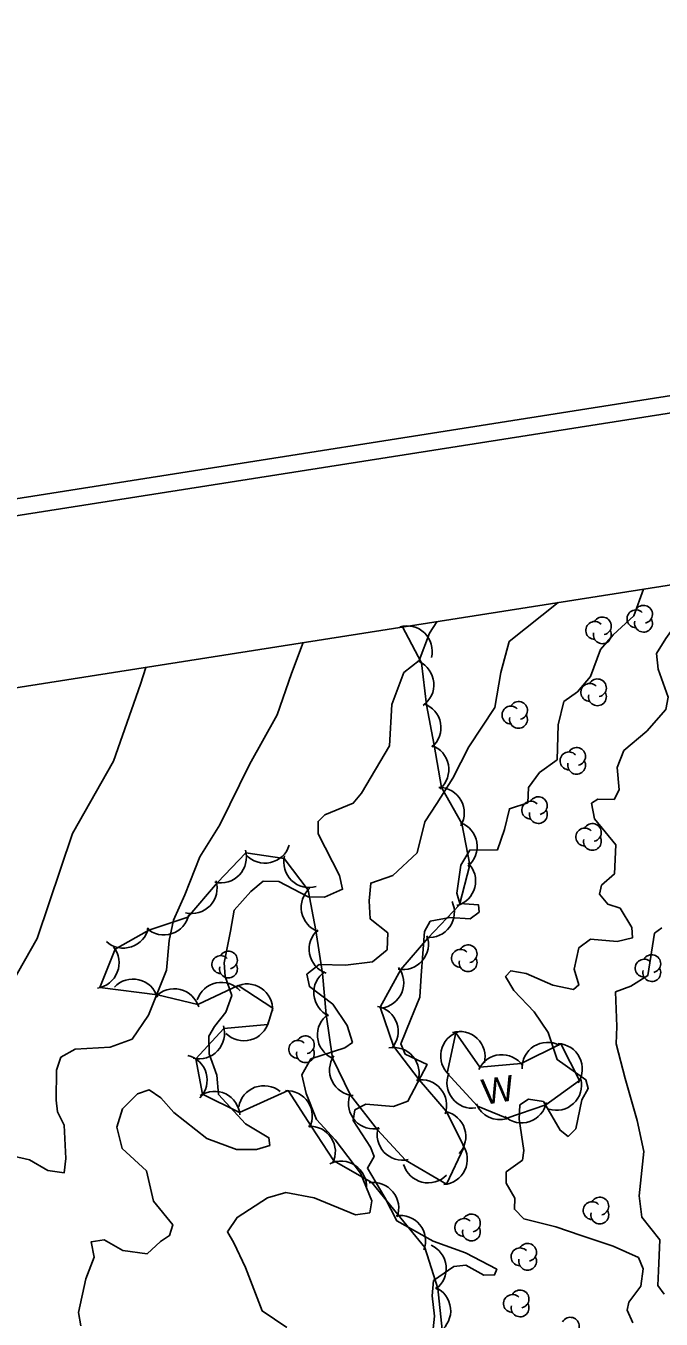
# Model space of a CAD drawing. Extents: x 646142 to 649934, y 5874075 to 5876351.
# Drawn here: x 646903.8 to 646978.6, y 5875820.6 to 5875973 of the extents above; entities that cross this region are included whole.
import ezdxf

# ---------------------------------------------------------------- set-up
doc = ezdxf.new("R2010")
doc.units = 0
for name, color, linetype in [('Niveau 1', 7, 'Continuous'), ('Niveau 2', 7, 'Continuous'), ('Niveau 44', 7, 'Continuous'), ('Niveau 60', 7, 'Continuous')]:
    doc.layers.add(name, color=color, linetype=linetype)

msp = doc.modelspace()

# ---------------------------------------------------------------- linework, layer by layer
at = {"layer": 'Niveau 1'}
for points in [[(646902.34, 5875839.82), (646904.22, 5875839.4), (646906.37, 5875838.15), (646908.3, 5875837.85), (646908.51, 5875839.56), (646908.32, 5875843.47), (646907.52, 5875845.06), (646907.37, 5875846.43), (646907.39, 5875849.96), (646907.92, 5875851.47), (646909.59, 5875852.42), (646913.71, 5875852.66), (646916.31, 5875853.6), (646918.24, 5875856.43), (646920.37, 5875861.72), (646920.68, 5875865.23), (646921.17, 5875867.6), (646922.52, 5875870.6), (646924.28, 5875875.09), (646926.63, 5875878.84), (646930.12, 5875885.96), (646933.4, 5875891.79), (646935.06, 5875896.68), (646936.43, 5875900.31)], [(646978.94, 5875823.57), (646978.2, 5875824.59), (646978.31, 5875826.32), (646978.45, 5875829.97), (646976.33, 5875832.63), (646976.01, 5875835.13), (646976.57, 5875840.37), (646975.79, 5875844.03), (646974.36, 5875848.96), (646973.3, 5875853.05), (646973.38, 5875855.08), (646973.24, 5875859.16), (646975.02, 5875859.85), (646977.02, 5875861.09), (646977.83, 5875866.07), (646977.83, 5875866.07), (646978.69, 5875866.73)]]:
    msp.add_lwpolyline(points, dxfattribs=at)
at = {"layer": 'Niveau 2'}
for points in [[(646971.57, 5875871.75), (646973.11, 5875873.06), (646973.28, 5875876.48), (646970.77, 5875879.57), (646970.41, 5875881.39), (646971.16, 5875881.87), (646973.07, 5875881.83), (646973.65, 5875882.98), (646973.43, 5875885.62), (646974.21, 5875887.6), (646976.92, 5875889.89), (646979.14, 5875892.43), (646979.45, 5875893.9), (646978.24, 5875897.19), (646978.05, 5875899.02), (646979.14, 5875900.8), (646980.66, 5875902.86), (646980.78, 5875905.65), (646982.82, 5875907.12), (646986.02, 5875908.02), (646988.53, 5875908.5)], [(646951.75, 5875829.82), (646947.49, 5875832.2), (646947.49, 5875832.2), (646946.05, 5875834.97), (646944.02, 5875838.42), (646944.79, 5875839.77), (646944.39, 5875840.88), (646942.33, 5875844.03), (646942.54, 5875845.27), (646943.84, 5875845.94), (646947.07, 5875845.68), (646948.78, 5875846.28), (646951.05, 5875850.63), (646948.47, 5875851.83), (646947.94, 5875853.04), (646949.11, 5875855.94), (646950.2, 5875858.54), (646950.33, 5875861.09), (646950.75, 5875866.27), (646951.41, 5875867.5), (646953.71, 5875867.94), (646956.13, 5875867.76), (646957.19, 5875868.57), (646957.1, 5875869.42), (646954.91, 5875869.57), (646954.55, 5875870.8), (646955, 5875874.08), (646956.06, 5875875.87), (646959.32, 5875875.9), (646960.14, 5875878.31), (646960.74, 5875880.74), (646962.89, 5875881.45), (646962.99, 5875883.25), (646964.28, 5875885.01), (646966.35, 5875886.52), (646966.48, 5875890.63), (646967.16, 5875893.36), (646968.75, 5875894.52), (646970.28, 5875896.31), (646971.48, 5875899.51), (646972.95, 5875901.24), (646975.4, 5875903.48), (646976.51, 5875906.61)], [(646966.47, 5875905.03), (646960.69, 5875900.43), (646959.73, 5875896.8), (646959, 5875892.67), (646955.94, 5875888.02), (646954.06, 5875884.35), (646952.17, 5875881.38), (646950.79, 5875879.2), (646949.86, 5875875.57), (646947, 5875872.87), (646944.4, 5875871.99), (646944.23, 5875869.9), (646944.34, 5875867.77), (646946.41, 5875866.11), (646946.34, 5875864.14), (646944.6, 5875862.73), (646941.44, 5875862.3), (646938.34, 5875862.4), (646936.86, 5875861.25), (646937.18, 5875859.79), (646939.93, 5875857.74), (646941.63, 5875855.23), (646942.24, 5875853.22), (646941.34, 5875852.6), (646937.36, 5875851.27), (646936.3, 5875849.41), (646936.82, 5875847.22), (646938.01, 5875844.13), (646940.22, 5875841.74), (646943.21, 5875837.82), (646944.54, 5875834.57), (646944.29, 5875833.16), (646942.6, 5875832.9), (646937.74, 5875834.93), (646934.42, 5875835.53), (646932.25, 5875834.93), (646928.66, 5875832.61), (646927.53, 5875830.92), (646928.3, 5875829.62), (646929.64, 5875826.72), (646931.62, 5875821.59), (646934.53, 5875819.63)], [(646917.98, 5875838.11), (646915.12, 5875840.73), (646914.5, 5875843.25), (646915.18, 5875845.41), (646916.94, 5875847.18), (646918.33, 5875847.63), (646919.69, 5875846.69), (646921.2, 5875844.96), (646925.09, 5875841.89), (646928.61, 5875840.62), (646930.96, 5875840.61), (646932.52, 5875841.08), (646932.42, 5875841.99), (646929.66, 5875843.63), (646926.48, 5875847.08), (646926.29, 5875849.37), (646925.39, 5875851.86), (646925.34, 5875853.94), (646926.01, 5875855.11), (646927.33, 5875856.77), (646928.03, 5875858.76), (646927.27, 5875860.98), (646927.16, 5875862.59), (646927.9, 5875866.32), (646928.32, 5875868.79), (646930.27, 5875870.98), (646931.74, 5875872.2), (646933.58, 5875872.18), (646937.05, 5875870.38), (646938.95, 5875870.32), (646941.08, 5875871.26), (646940.73, 5875872.89), (646938.2, 5875877.8), (646938.21, 5875879.25), (646938.99, 5875880.04), (646942.34, 5875881.41), (646943.31, 5875882.56), (646946.61, 5875888.15), (646946.89, 5875893.04), (646948.32, 5875896.79), (646950.12, 5875898.22), (646951.32, 5875901.42), (646952.17, 5875902.78)], [(646917.91, 5875897.39), (646917.28, 5875895.43), (646914.11, 5875886.36), (646909.27, 5875877.84), (646905.14, 5875865.47), (646899.96, 5875856.4)], [(646975.28, 5875820.2), (646974.61, 5875821.69), (646974.8, 5875822.63), (646976.22, 5875824.51), (646976.47, 5875826.55), (646975.93, 5875827.88), (646972.97, 5875829.2), (646969.2, 5875830.49), (646966.21, 5875831.51), (646962.42, 5875832.45), (646961.32, 5875833.56), (646961.36, 5875834.89), (646960.37, 5875836.63), (646960.35, 5875837.96), (646962.28, 5875839.36), (646962.28, 5875839.36), (646962.45, 5875840.48), (646961.9, 5875844.17), (646961.96, 5875845.85), (646962.98, 5875846.53), (646964.74, 5875846.24), (646966.71, 5875842.87), (646967.65, 5875842.15), (646968.54, 5875843.05), (646969.28, 5875846.47), (646970.01, 5875847.81), (646969.73, 5875848.82), (646966.37, 5875851.2), (646965.29, 5875854.38), (646963.65, 5875856.81), (646961.25, 5875859.34), (646960.28, 5875860.97), (646960.9, 5875861.67), (646962.72, 5875861.33), (646965.86, 5875859.97), (646968.28, 5875859.47), (646968.92, 5875859.99), (646968.38, 5875861.84), (646968.93, 5875864.38), (646970.27, 5875865.38), (646973.41, 5875865.12), (646975.22, 5875865.53), (646975.15, 5875866.74), (646973.76, 5875869.02), (646972.32, 5875869.51), (646971.34, 5875870.68), (646971.57, 5875871.75)], [(646910.26, 5875819.83), (646909.98, 5875821.41), (646909.98, 5875821.41), (646910.87, 5875825.38), (646911.85, 5875827.93), (646911.49, 5875829.73), (646913.01, 5875829.97), (646915.21, 5875828.72), (646918.07, 5875828.3), (646919.63, 5875829.76), (646920.7, 5875830.46), (646921.08, 5875831.72), (646918.83, 5875834.51), (646917.98, 5875838.11)], [(646951.58, 5875817.6), (646951.9, 5875820.98), (646951.64, 5875823.36), (646951.79, 5875825.16), (646954.18, 5875826.82), (646955.59, 5875826.99), (646957.72, 5875825.8), (646958.98, 5875825.83), (646959.25, 5875826.49), (646955.56, 5875828.42), (646951.75, 5875829.82)]]:
    msp.add_lwpolyline(points, dxfattribs=at)
at = {"layer": 'Niveau 44'}
for points in [[(646927.12, 5875854.86), (646932.27, 5875855.34), (646932.86, 5875857.27), (646928.79, 5875859.91), (646924.04, 5875857.7), (646919.31, 5875858.81), (646912.52, 5875859.69), (646914.3, 5875864.2), (646918.27, 5875866.45), (646922.88, 5875867.97), (646926.36, 5875872.04), (646929.71, 5875875.56), (646934.2, 5875874.88), (646937.02, 5875871.16), (646937.93, 5875866.4), (646938.73, 5875861.35), (646939.15, 5875856.51), (646939.9, 5875851.37), (646942.02, 5875847), (646945.22, 5875842.93), (646948.51, 5875839.36), (646953.32, 5875836.51), (646955.4, 5875840.9), (646953.27, 5875845.12), (646950.11, 5875848.81), (646947.1, 5875852.79), (646945.52, 5875857.38), (646947.96, 5875861.8), (646951.12, 5875865.49), (646954.86, 5875869.44), (646956.07, 5875874.14), (646955.15, 5875879.02), (646952.75, 5875883.24), (646951.86, 5875888.23), (646950.97, 5875893), (646950.39, 5875897.94), (646948.12, 5875902.25)], [(646952.83, 5875819.39), (646952.31, 5875824.22), (646950.77, 5875829.08), (646947.6, 5875832.95), (646944.53, 5875836.71), (646940.04, 5875839.27), (646937.4, 5875843.34), (646934.67, 5875847.54), (646928.96, 5875844.98), (646924.6, 5875847.11), (646923.82, 5875851.3), (646927.12, 5875854.86)], [(646954.42, 5875854.35), (646953.4, 5875849.6), (646956.98, 5875845.71), (646960.43, 5875844.29), (646965.02, 5875845.85), (646968.99, 5875848.73), (646966.79, 5875853.06), (646962.11, 5875850.74), (646957.27, 5875850.32), (646954.42, 5875854.35)]]:
    msp.add_lwpolyline(points, dxfattribs=at)
for centre, radius, start, end in [((646975.63, 5875903.12), 1.05, 44.1154, 269.804), ((646976.53, 5875903.65), 1.05, 282.2692, 149.7263), ((646948.65, 5875899.29), 3, 346.0604, 106.0383), ((646970.78, 5875901.75), 1.05, 44.1154, 269.804), ((646971.68, 5875902.28), 1.05, 282.2692, 149.7263), ((646976.53, 5875902.6), 1.05, 166.9369, 29.6212), ((646971.68, 5875901.23), 1.05, 166.9369, 29.6212), ((646948.84, 5875895.36), 3, 305.0204, 64.9984), ((646971.1, 5875894.98), 1.05, 282.2692, 149.7263), ((646970.2, 5875894.45), 1.05, 44.1154, 269.804), ((646971.1, 5875893.93), 1.05, 166.9369, 29.6212), ((646949.68, 5875890.29), 3, 310.6472, 70.6251), ((646961.81, 5875892.32), 1.05, 282.2692, 149.7263), ((646960.91, 5875891.79), 1.05, 44.1154, 269.804), ((646961.81, 5875891.27), 1.05, 166.9369, 29.6212), ((646950.6, 5875885.38), 3, 310.6472, 70.6251), ((646967.75, 5875886.38), 1.05, 44.1154, 269.804), ((646968.65, 5875886.91), 1.05, 282.2692, 149.7263), ((646968.65, 5875885.86), 1.05, 166.9369, 29.6212), ((646952.42, 5875880.26), 3, 329.6122, 89.5901), ((646963.24, 5875880.58), 1.05, 44.1154, 269.804), ((646964.14, 5875881.11), 1.05, 282.2692, 149.7263), ((646964.14, 5875880.06), 1.05, 166.9369, 29.6212), ((646953.94, 5875876.29), 3, 309.6291, 69.607), ((646969.61, 5875877.42), 1.05, 44.1154, 269.804), ((646970.51, 5875877.95), 1.05, 282.2692, 149.7263), ((646931.94, 5875877.34), 3, 222.5405, 342.5185), ((646970.51, 5875876.9), 1.05, 166.9369, 29.6212), ((646926.76, 5875875.01), 3, 256.4495, 16.4274), ((646937.17, 5875874.46), 3, 165.8167, 285.7946), ((646953.76, 5875872.23), 3, 285.4897, 45.4677), ((646923.31, 5875871.39), 3, 256.4495, 16.4274), ((646939.21, 5875869.11), 3, 130.8458, 250.8238), ((646951.26, 5875868.56), 3, 264.663, 24.6409), ((646920.03, 5875868.88), 3, 228.1764, 348.1543), ((646915.28, 5875867.33), 3, 228.1764, 348.1543), ((646940.15, 5875864.2), 3, 130.8458, 250.8238), ((646948.2, 5875864.79), 3, 259.3849, 19.3629), ((646911.77, 5875862.59), 3, 278.465, 38.4429), ((646927.65, 5875862.92), 1.05, 282.2692, 149.7263), ((646954.97, 5875863.13), 1.05, 44.1154, 269.804), ((646955.87, 5875863.66), 1.05, 282.2692, 149.7263), ((646926.75, 5875862.39), 1.05, 44.1154, 269.804), ((646955.87, 5875862.61), 1.05, 166.9369, 29.6212), ((646976.6, 5875861.97), 1.05, 44.1154, 269.804), ((646977.5, 5875862.5), 1.05, 282.2692, 149.7263), ((646927.65, 5875861.87), 1.05, 166.9369, 29.6212), ((646940.7, 5875859.08), 3, 124.9549, 244.9328), ((646945.29, 5875860.24), 3, 277.1476, 37.1255), ((646977.5, 5875861.45), 1.05, 166.9369, 29.6212), ((646916.41, 5875857.68), 3, 16.7659, 136.7438), ((646921.27, 5875856.54), 3, 16.7659, 136.7438), ((646926.82, 5875857.3), 3, 42.0929, 162.0708), ((646929.86, 5875857.11), 3, 356.9531, 116.9311), ((646941.13, 5875854.1), 3, 124.9549, 244.9328), ((646944.64, 5875854.52), 3, 318.9121, 78.89), ((646924.18, 5875854.28), 3, 257.0633, 17.0412), ((646929.47, 5875856.41), 3, 225.0286, 345.0066), ((646935.81, 5875852.41), 1.05, 44.1154, 269.804), ((646936.71, 5875852.94), 1.05, 282.2692, 149.7263), ((646955.64, 5875851.61), 3, 107.8808, 227.8588), ((646954.87, 5875851.51), 3, 346.4924, 106.4704), ((646936.71, 5875851.89), 1.05, 166.9369, 29.6212), ((646947.1, 5875849.62), 3, 340.5702, 100.5481), ((646959.84, 5875848.77), 3, 34.9178, 154.8957), ((646965.23, 5875850.23), 3, 62.5794, 182.5573), ((646966.32, 5875850.09), 3, 326.9361, 86.9141), ((646922.14, 5875848.78), 3, 315.8635, 75.8414), ((646942.55, 5875849.96), 3, 145.9962, 265.9742), ((646950.35, 5875845.82), 3, 340.5702, 100.5481), ((646956.38, 5875848.47), 3, 158.0342, 278.0122), ((646966.24, 5875848.22), 3, 253.044, 13.022), ((646926.01, 5875844.46), 3, 4.0141, 123.992), ((646931.82, 5875845.12), 3, 50.4213, 170.3992), ((646934.52, 5875844.54), 3, 333.0239, 93.0019), ((646944.78, 5875846.02), 3, 162.6758, 282.6538), ((646959.63, 5875847.12), 3, 202.0773, 285.7892), ((646962.16, 5875846.74), 3, 228.7511, 348.7291), ((646952.6, 5875842.13), 3, 317.7895, 77.7675), ((646937.24, 5875840.35), 3, 333.0239, 93.0019), ((646948.16, 5875842.34), 3, 162.6758, 282.6538), ((646952.77, 5875839.46), 3, 274.5316, 34.5096), ((646940.91, 5875836.24), 3, 356.1073, 116.0853), ((646951.17, 5875839.67), 3, 195.7151, 315.693), ((646944.7, 5875833.72), 3, 339.2617, 99.2396), ((646971.38, 5875833.94), 1.05, 282.2692, 149.7263), ((646970.48, 5875833.41), 1.05, 44.1154, 269.804), ((646947.87, 5875829.84), 3, 339.2617, 99.2396), ((646955.36, 5875831.42), 1.05, 44.1154, 269.804), ((646956.26, 5875831.95), 1.05, 282.2692, 149.7263), ((646971.38, 5875832.89), 1.05, 166.9369, 29.6212), ((646956.26, 5875830.9), 1.05, 166.9369, 29.6212), ((646950.29, 5875826.59), 3, 306.1562, 66.1341), ((646961.98, 5875827.96), 1.05, 44.1154, 269.804), ((646962.88, 5875828.49), 1.05, 282.2692, 149.7263), ((646962.88, 5875827.44), 1.05, 166.9369, 29.6212), ((646950.82, 5875821.61), 3, 306.1562, 66.1341), ((646961.09, 5875822.47), 1.05, 44.1154, 269.804), ((646961.99, 5875823), 1.05, 282.2692, 149.7263), ((646961.99, 5875821.95), 1.05, 166.9369, 29.6212), ((646967.91, 5875819.79), 1.05, 282.2692, 149.7263)]:
    msp.add_arc(centre, radius, start, end, dxfattribs=at)
at = {"layer": 'Niveau 60'}
for points in [[(646142.26, 5875797.64), (649662.59, 5876351.49), (649933.58, 5874629.01), (646413.32, 5874074.83), (646142.26, 5875797.64)], [(646144.55, 5875795.97), (649660.92, 5876349.21), (649931.28, 5874630.65), (646414.98, 5874077.12), (646144.55, 5875795.97)]]:
    msp.add_lwpolyline(points, dxfattribs=at)
msp.add_lwpolyline([(646167.42, 5875779.32), (649130.97, 5876245.57), (649395.18, 5874566.24), (646431.63, 5874099.99)], close=True, dxfattribs=at)
msp.add_lwpolyline([(646167.42, 5875779.32), (649130.97, 5876245.57), (649395.18, 5874566.24), (646431.63, 5874099.99)], close=True, dxfattribs=at)

# ---------------------------------------------------------------- texts
at = {"layer": 'Niveau 44'}
msp.add_text('W', height=3, rotation=8.9405, dxfattribs=at).set_placement((646957.74, 5875845.85))

doc.saveas('drawing.dxf')
